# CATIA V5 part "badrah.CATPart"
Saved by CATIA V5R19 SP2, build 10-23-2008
Part number: badrah
Bounding box of the stored display mesh (mm): x -1336.914 to -1077, y -529.41 to 529.41, z 54.942 to 379.609
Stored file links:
  C:\BEHROOZ\catia learning\tarh haye mashin\hb\badrah.CATPart
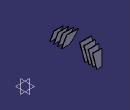
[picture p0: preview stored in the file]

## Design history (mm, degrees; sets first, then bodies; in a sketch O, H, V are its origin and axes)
Body1 (main body)
  Plane1: stored without definition
  DatumSurface1 to DatumSurface5
  Sketch1 on Plane1, origin (-1447, 0, 0), H (0, 1, 0), V (0, 0, 1)
    line L1 (258.4455, 54.9421) -> (140.3108, 379.6087)
    line L2 (140.3108, 379.6087) -> (150.9428, 379.6087)
    line L3 (150.9428, 379.6087) -> (269.0774, 54.9421)
    line L4 (269.0774, 54.9421) -> (258.4455, 54.9421)
    line L5 (345.2229, 56.2636) -> (233.4287, 363.505)
    line L6 (233.4287, 363.505) -> (244.0606, 363.505)
    line L7 (244.0606, 363.505) -> (355.8548, 56.2636)
    line L8 (355.8548, 56.2636) -> (345.2229, 56.2636)
    line L9 (432.0003, 57.5851) -> (329.1657, 340.2031)
    line L10 (329.1657, 340.2031) -> (339.7976, 340.2031)
    line L11 (339.7976, 340.2031) -> (442.6322, 57.5851)
    line L12 (442.6322, 57.5851) -> (432.0003, 57.5851)
    line L13 (518.7777, 58.9067) -> (426.1599, 313.4459)
    line L14 (426.1599, 313.4459) -> (436.7918, 313.4459)
    line L15 (436.7918, 313.4459) -> (529.4096, 58.9067)
    line L16 (529.4096, 58.9067) -> (518.7777, 58.9067)
    line L17 (-258.4455, 54.9421) -> (-140.3108, 379.6087)
    line L18 (-140.3108, 379.6087) -> (-150.9428, 379.6087)
    line L19 (-150.9428, 379.6087) -> (-269.0774, 54.9421)
    line L20 (-269.0774, 54.9421) -> (-258.4455, 54.9421)
    line L21 (-345.2229, 56.2636) -> (-233.4287, 363.505)
    line L22 (-233.4287, 363.505) -> (-244.0606, 363.505)
    line L23 (-244.0606, 363.505) -> (-355.8548, 56.2636)
    line L24 (-355.8548, 56.2636) -> (-345.2229, 56.2636)
    line L25 (-432.0003, 57.5851) -> (-329.1657, 340.2031)
    line L26 (-329.1657, 340.2031) -> (-339.7976, 340.2031)
    line L27 (-339.7976, 340.2031) -> (-442.6322, 57.5851)
    line L28 (-442.6322, 57.5851) -> (-432.0003, 57.5851)
    line L29 (-518.7777, 58.9067) -> (-426.1599, 313.4459)
    line L30 (-426.1599, 313.4459) -> (-436.7918, 313.4459)
    line L31 (-436.7918, 313.4459) -> (-529.4096, 58.9067)
    line L32 (-529.4096, 58.9067) -> (-518.7777, 58.9067)
  Pad1: profile Sketch1, direction (1, 0, 0), length 370
  Sketch2 on zx-plane, origin (0, 0, 0), H (-1, 0, 0), V (0, 0, 1)
    arc A1 centre (39.5603, 484.72) radius 1307.7229 from (1346.3058, 434.1706) to (1234.1097, -47.4368) cw
    line L1 (1234.1097, -47.4368) -> (1673.3386, -82.0838)
    line L2 (1673.3386, -82.0838) -> (1588.6694, 421.7517)
    line L3 (1588.6694, 421.7517) -> (1346.3058, 434.1706)
  DatumCurve1 to DatumCurve5
  Sketch3 on xy-plane, origin (0, 0, 0), H (1, 0, 0), V (0, 1, 0)
    arc A1 centre (263.7692, 0) radius 1609.403 from (-1230.4076, -598.0082) to (-1230.4076, 598.0082) cw
  Slot1: profile Sketch2, centre curve Sketch3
